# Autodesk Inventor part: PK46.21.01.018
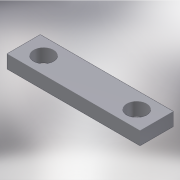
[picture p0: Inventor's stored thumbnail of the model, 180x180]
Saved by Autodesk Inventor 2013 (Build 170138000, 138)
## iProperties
Created: 2005-04
Part Number: PK46.21.01.018
Material: Steel, Mild
Document SubType Name: Modeling
Designer: salex
Manufacturer: Standard
Standards Organization: Custom
Density: 7.86 g/cm^3
Author: salex
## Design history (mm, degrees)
sketch "Эскиз1"
  geometry: L1 (0, 0)-(200, 0); L2 (200, 0)-(200, 50); L3 (200, 50)-(0, 50); L4 (0, 50)-(0, 0); C1 r 15 at (30, 25); C2 r 15 at (170, 25)
  constraints: 8 end point, 2 centre point, 2 parallel, 1 equal radius, 1 horizontal, 1 perpendicular, 1 other
  dimensions: "d0" = 200 distance between parallel lines of L2 L4; "d1" = 50 distance of L3.end L1.start; "d2" = 140 distance of C2.centre C1.centre; "d3" = 0 vertical distance of C2.centre C1.centre; "d4" = 25 distance from line of L1 C1.centre (= 0.5 x d1); "d5" = 30 diameter of C1; "d6" = 30 distance from line of L4 C1.centre
extrude "Выдавливание1" new body sketch "Эскиз1" distance "d7" = 20; taper "d8" = 0 deg
body "Solid1"
